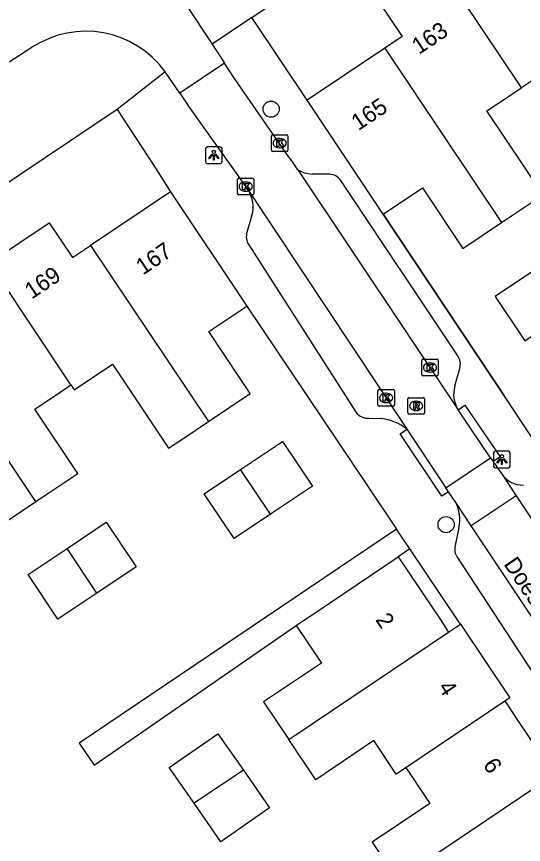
# Model space of a CAD drawing. Extents: x 158352 to 159489, y 383828 to 384597.
# Drawn here: x 158835 to 158865.6, y 384167.6 to 384217.6 of the extents above; entities that cross this region are included whole.
import ezdxf

# ---------------------------------------------------------------- set-up
doc = ezdxf.new("R2010")
doc.units = 0
for name, color, linetype in [('IMGEO_Boom', 7, 'Continuous'), ('IMGEO_Kolk', 7, 'Continuous'), ('IMGEO_Lichtpunt', 7, 'Continuous'), ('IMGEO_Muur', 7, 'Continuous'), ('IMGEO_Openbare_ruimte_label', 7, 'Continuous'), ('IMGEO_Pand', 7, 'Continuous'), ('IMGEO_Pand_nummerreeks', 7, 'Continuous'), ('IMGEO_Rijbaan_lokaal_open', 7, 'Continuous'), ('IMGEO_Rioolput', 7, 'Continuous'), ('IMGEO_Voetpad_open', 7, 'Continuous')]:
    doc.layers.add(name, color=color, linetype=linetype)

msp = doc.modelspace()

# ---------------------------------------------------------------- linework, layer by layer
at = {"layer": 'IMGEO_Boom'}
for centre in [(158850.367, 384212.043), (158860.955, 384186.927)]:
    msp.add_circle(centre, 0.489, dxfattribs=at)
at = {"layer": 'IMGEO_Kolk'}
for p, q in [((158850.381, 384209.562), (158850.381, 384210.414)), ((158850.456, 384210.488), (158851.308, 384210.488)), ((158850.869, 384210.268), (158850.894, 384210.268)), ((158851.382, 384210.414), (158851.382, 384209.562)), ((158850.892, 384209.708), (158850.867, 384209.708)), ((158851.308, 384209.488), (158850.456, 384209.488)), ((158848.323, 384206.935), (158848.323, 384207.787)), ((158848.398, 384207.861), (158849.25, 384207.861)), ((158848.811, 384207.641), (158848.836, 384207.641)), ((158849.324, 384207.787), (158849.324, 384206.935)), ((158848.834, 384207.081), (158848.809, 384207.081)), ((158849.25, 384206.861), (158848.398, 384206.861)), ((158859.482, 384195.998), (158859.482, 384196.85)), ((158859.557, 384196.924), (158860.409, 384196.924)), ((158859.97, 384196.704), (158859.995, 384196.704)), ((158860.483, 384196.85), (158860.483, 384195.998)), ((158859.993, 384196.144), (158859.968, 384196.144)), ((158860.409, 384195.924), (158859.557, 384195.924)), ((158856.899, 384195.086), (158857.751, 384195.086)), ((158856.824, 384194.16), (158856.824, 384195.012)), ((158857.312, 384194.866), (158857.337, 384194.866)), ((158857.825, 384195.012), (158857.825, 384194.16)), ((158857.751, 384194.086), (158856.899, 384194.086)), ((158857.335, 384194.306), (158857.31, 384194.306))]:
    msp.add_line(p, q, dxfattribs=at)
for points in [[(158850.381, 384209.562), (158850.381, 384210.414)], [(158850.456, 384210.488), (158851.308, 384210.488)], [(158850.702, 384210.188), (158850.825, 384210.188), (158850.825, 384210.037), (158850.955, 384210.188), (158851.119, 384210.188), (158850.973, 384210.037), (158851.126, 384209.788), (158850.974, 384209.788), (158850.889, 384209.952), (158850.825, 384209.885), (158850.825, 384209.788), (158850.702, 384209.788), (158850.702, 384210.188)], [(158851.382, 384210.414), (158851.382, 384209.562)], [(158851.308, 384209.488), (158850.456, 384209.488)], [(158848.323, 384206.935), (158848.323, 384207.787)], [(158848.398, 384207.861), (158849.25, 384207.861)], [(158849.324, 384207.787), (158849.324, 384206.935)], [(158848.644, 384207.561), (158848.767, 384207.561), (158848.767, 384207.41), (158848.897, 384207.561), (158849.061, 384207.561), (158848.915, 384207.41), (158849.068, 384207.161), (158848.916, 384207.161), (158848.831, 384207.325), (158848.767, 384207.258), (158848.767, 384207.161), (158848.644, 384207.161), (158848.644, 384207.561)], [(158849.25, 384206.861), (158848.398, 384206.861)], [(158859.482, 384195.998), (158859.482, 384196.85)], [(158859.557, 384196.924), (158860.409, 384196.924)], [(158859.803, 384196.624), (158859.926, 384196.624), (158859.926, 384196.473), (158860.056, 384196.624), (158860.22, 384196.624), (158860.074, 384196.473), (158860.227, 384196.224), (158860.075, 384196.224), (158859.99, 384196.388), (158859.926, 384196.321), (158859.926, 384196.224), (158859.803, 384196.224), (158859.803, 384196.624)], [(158860.483, 384196.85), (158860.483, 384195.998)], [(158860.409, 384195.924), (158859.557, 384195.924)], [(158856.899, 384195.086), (158857.751, 384195.086)], [(158856.824, 384194.16), (158856.824, 384195.012)], [(158857.145, 384194.786), (158857.268, 384194.786), (158857.268, 384194.635), (158857.398, 384194.786), (158857.562, 384194.786), (158857.416, 384194.635), (158857.569, 384194.386), (158857.417, 384194.386), (158857.332, 384194.55), (158857.268, 384194.483), (158857.268, 384194.386), (158857.145, 384194.386), (158857.145, 384194.786)], [(158857.825, 384195.012), (158857.825, 384194.16)], [(158857.751, 384194.086), (158856.899, 384194.086)]]:
    msp.add_lwpolyline(points, dxfattribs=at)
for centre, start, end in [((158850.458, 384210.412), 91.552, 178.448), ((158850.458, 384210.412), 91.552, 178.448), ((158851.306, 384210.412), 1.552, 88.448), ((158851.306, 384210.412), 1.552, 88.448), ((158850.458, 384209.564), 181.552, 268.448), ((158850.458, 384209.564), 181.552, 268.448), ((158851.306, 384209.564), 271.552, 358.448), ((158851.306, 384209.564), 271.552, 358.448), ((158848.4, 384207.785), 91.552, 178.448), ((158848.4, 384207.785), 91.552, 178.448), ((158849.248, 384207.785), 1.552, 88.448), ((158849.248, 384207.785), 1.552, 88.448), ((158848.4, 384206.937), 181.552, 268.448), ((158848.4, 384206.937), 181.552, 268.448), ((158849.248, 384206.937), 271.552, 358.448), ((158849.248, 384206.937), 271.552, 358.448), ((158859.559, 384196.848), 91.552, 178.448), ((158859.559, 384196.848), 91.552, 178.448), ((158860.407, 384196.848), 1.552, 88.448), ((158860.407, 384196.848), 1.552, 88.448), ((158859.559, 384196), 181.552, 268.448), ((158859.559, 384196), 181.552, 268.448), ((158860.407, 384196), 271.552, 358.448), ((158860.407, 384196), 271.552, 358.448), ((158856.901, 384195.01), 91.552, 178.448), ((158856.901, 384195.01), 91.552, 178.448), ((158857.749, 384195.01), 1.552, 88.448), ((158857.749, 384195.01), 1.552, 88.448), ((158856.901, 384194.162), 181.552, 268.448), ((158856.901, 384194.162), 181.552, 268.448), ((158857.749, 384194.162), 271.552, 358.448), ((158857.749, 384194.162), 271.552, 358.448)]:
    msp.add_arc(centre, 0.0765, start, end, dxfattribs=at)
for centre, major_axis, ratio, start_param, end_param in [((158850.868, 384209.988), (-0.387, 0.002), 0.722429, 4.712389, 7.853982), ((158850.893, 384209.988), (-0.39, 0.002), 0.717154, 1.570796, 4.712389), ((158848.81, 384207.361), (-0.387, 0.002), 0.722429, 4.712389, 7.853982), ((158848.835, 384207.361), (-0.39, 0.002), 0.717154, 1.570796, 4.712389), ((158859.969, 384196.424), (-0.387, 0.002), 0.722429, 4.712389, 7.853982), ((158859.994, 384196.424), (-0.39, 0.002), 0.717154, 1.570796, 4.712389), ((158857.311, 384194.586), (-0.387, 0.002), 0.722429, 4.712389, 7.853982), ((158857.336, 384194.586), (-0.39, 0.002), 0.717154, 1.570796, 4.712389)]:
    msp.add_ellipse(centre, major_axis=major_axis, ratio=ratio, start_param=start_param, end_param=end_param, dxfattribs=at)
at = {"layer": 'IMGEO_Lichtpunt'}
for p, q in [((158846.4, 384209.659), (158846.4, 384208.852)), ((158846.4, 384209.659), (158846.4, 384208.852)), ((158847.302, 384209.754), (158846.494, 384209.754)), ((158847.302, 384209.754), (158846.494, 384209.754)), ((158847.396, 384208.852), (158847.396, 384209.659)), ((158847.396, 384208.852), (158847.396, 384209.659)), ((158846.494, 384208.758), (158847.302, 384208.758)), ((158846.494, 384208.758), (158847.302, 384208.758)), ((158863.831, 384191.264), (158863.831, 384190.457)), ((158863.831, 384191.264), (158863.831, 384190.457)), ((158864.733, 384191.359), (158863.925, 384191.359)), ((158864.733, 384191.359), (158863.925, 384191.359)), ((158864.827, 384190.457), (158864.827, 384191.264)), ((158864.827, 384190.457), (158864.827, 384191.264)), ((158863.925, 384190.363), (158864.733, 384190.363)), ((158863.925, 384190.363), (158864.733, 384190.363))]:
    msp.add_line(p, q, dxfattribs=at)
for points in [[(158846.774, 384209.323), (158846.813, 384209.295), (158846.625, 384209.033), (158846.587, 384209.06), (158846.774, 384209.323)], [(158846.876, 384209.275), (158846.923, 384209.275), (158846.923, 384208.953), (158846.876, 384208.953), (158846.876, 384209.275)], [(158846.986, 384209.295), (158847.024, 384209.322), (158847.211, 384209.06), (158847.172, 384209.032), (158846.986, 384209.295)], [(158864.205, 384190.928), (158864.244, 384190.9), (158864.056, 384190.638), (158864.018, 384190.665), (158864.205, 384190.928)], [(158864.307, 384190.88), (158864.354, 384190.88), (158864.354, 384190.558), (158864.307, 384190.558), (158864.307, 384190.88)], [(158864.417, 384190.9), (158864.455, 384190.927), (158864.642, 384190.665), (158864.603, 384190.637), (158864.417, 384190.9)]]:
    msp.add_lwpolyline(points, dxfattribs=at)
for centre in [(158846.899, 384209.457), (158864.33, 384191.062)]:
    msp.add_circle(centre, 0.0994, dxfattribs=at)
for centre, start, end in [((158846.494, 384209.659), 90, 180), ((158846.494, 384209.659), 90, 180), ((158847.302, 384209.659), 0, 90), ((158847.302, 384209.659), 0, 90), ((158846.494, 384208.852), 180, 270), ((158846.494, 384208.852), 180, 270), ((158847.302, 384208.852), 270, 0), ((158847.302, 384208.852), 270, 360), ((158863.925, 384191.264), 90, 180), ((158863.925, 384191.264), 90, 180), ((158864.733, 384191.264), 0, 90), ((158864.733, 384191.264), 0, 90), ((158863.925, 384190.457), 180, 270), ((158863.925, 384190.457), 180, 270), ((158864.733, 384190.457), 270, 0), ((158864.733, 384190.457), 270, 360)]:
    msp.add_arc(centre, 0.0946, start, end, dxfattribs=at)
at = {"layer": 'IMGEO_Muur'}
for points in [[(158857.143, 384205.697), (158864.445, 384194.753)], [(158848.89, 384200.127), (158856.194, 384189.271)]]:
    msp.add_lwpolyline(points, dxfattribs=at)
at = {"layer": 'IMGEO_Pand'}
for points in [[(158860.858, 384220.299), (158860.447, 384220.913), (158856.885, 384218.53), (158858.292, 384216.428), (158857.246, 384215.728)], [(158865.517, 384213.338), (158865.421, 384213.482), (158860.858, 384220.299)], [(158857.246, 384215.728), (158852.538, 384212.577)], [(158857.246, 384215.728), (158864.304, 384205.184)], [(158870.027, 384211.237), (158869.947, 384211.183), (158867.58, 384214.719), (158865.517, 384213.338)], [(158864.304, 384205.184), (158866.129, 384206.406), (158866.824, 384206.871), (158863.43, 384211.941), (158865.517, 384213.338)], [(158857.143, 384205.697), (158852.538, 384212.577)], [(158857.143, 384205.697), (158859.52, 384207.288), (158861.974, 384203.624), (158864.304, 384205.184)], [(158844.268, 384207.036), (158839.443, 384203.809)], [(158844.268, 384207.036), (158848.89, 384200.127)], [(158833.777, 384202.052), (158833.309, 384202.752), (158836.934, 384205.178), (158838.343, 384203.073), (158839.443, 384203.809)], [(158839.443, 384203.809), (158846.568, 384193.158)], [(158866.251, 384202.276), (158863.921, 384200.716), (158865.718, 384198.032), (158868.047, 384199.592)], [(158838.25, 384195.367), (158838.209, 384195.428), (158833.777, 384202.052)], [(158846.568, 384193.158), (158849.108, 384194.859), (158846.605, 384198.598), (158848.89, 384200.127)], [(158836.124, 384188.317), (158835.871, 384188.696), (158829.052, 384198.891)], [(158838.25, 384195.367), (158838.444, 384195.077), (158840.76, 384196.626), (158844.159, 384191.546), (158844.954, 384192.078), (158846.568, 384193.158)], [(158836.124, 384188.317), (158838.661, 384190.014), (158836.059, 384193.902), (158837.602, 384194.934), (158838.101, 384195.267), (158838.25, 384195.367)], [(158848.514, 384190.249), (158851.055, 384191.95), (158852.863, 384189.249), (158850.321, 384187.548)], [(158828.991, 384188.758), (158831.225, 384190.253), (158833.634, 384186.651), (158836.124, 384188.317)], [(158850.321, 384187.548), (158848.127, 384186.079), (158846.319, 384188.78), (158848.514, 384190.249)], [(158850.321, 384187.548), (158848.514, 384190.249)], [(158838.017, 384185.488), (158840.39, 384187.076), (158842.198, 384184.375), (158839.824, 384182.786)], [(158839.824, 384182.786), (158837.462, 384181.205), (158835.654, 384183.906), (158838.017, 384185.488)], [(158839.824, 384182.786), (158838.017, 384185.488)], [(158851.882, 384180.832), (158853.899, 384182.187), (158858.049, 384184.975)], [(158858.049, 384184.975), (158860.667, 384181.079), (158861.009, 384180.57), (158861.106, 384180.426)], [(158851.882, 384180.832), (158853.411, 384178.559), (158849.91, 384176.206), (158851.438, 384173.932)], [(158861.106, 384180.426), (158861.821, 384180.907)], [(158861.821, 384180.907), (158864.81, 384176.459), (158864.513, 384176.259)], [(158851.438, 384173.932), (158851.682, 384174.096), (158861.106, 384180.426)], [(158864.513, 384176.259), (158858.517, 384172.232)], [(158864.513, 384176.259), (158864.588, 384176.147), (158865.246, 384175.168), (158867.501, 384171.811)], [(158845.706, 384170.082), (158844.204, 384172.235), (158847.151, 384174.283), (158848.685, 384172.083)], [(158858.517, 384172.232), (158857.94, 384171.845), (158856.581, 384173.868), (158853.067, 384171.507), (158851.438, 384173.932)], [(158848.685, 384172.083), (158845.706, 384170.082)], [(158848.685, 384172.083), (158850.275, 384169.804), (158847.328, 384167.756), (158845.706, 384170.082)], [(158858.517, 384172.232), (158858.716, 384171.937), (158858.956, 384171.581), (158859.97, 384170.072), (158856.487, 384167.731), (158858.024, 384165.444)], [(158858.024, 384165.444), (158858.355, 384165.667), (158867.501, 384171.811)]]:
    msp.add_lwpolyline(points, dxfattribs=at)
at = {"layer": 'IMGEO_Rijbaan_lokaal_open'}
for points in [[(158845.198, 384218.378), (158846.791, 384215.962)], [(158835.895, 384215.779), (158834.508, 384214.879)], [(158846.791, 384215.962), (158847.546, 384214.816)], [(158847.546, 384214.816), (158844.837, 384213.001)], [(158851.983, 384208.383), (158851.589, 384208.974), (158851.354, 384209.268), (158848.141, 384213.898), (158847.546, 384214.816)], [(158844.837, 384213.001), (158843.962, 384214.297)], [(158844.837, 384213.001), (158845.444, 384212.097), (158848.992, 384207.115)], [(158851.983, 384208.383), (158861.676, 384193.862)], [(158848.992, 384207.115), (158858.439, 384192.912), (158858.586, 384192.689)], [(158863.65, 384190.966), (158861.676, 384193.862)], [(158858.586, 384192.689), (158860.943, 384189.158)], [(158860.943, 384189.158), (158863.65, 384190.966)], [(158863.65, 384190.966), (158863.807, 384190.736)], [(158863.807, 384190.736), (158864.301, 384190.011)], [(158864.301, 384190.011), (158865.197, 384188.669)], [(158861.106, 384188.914), (158860.943, 384189.158)], [(158861.542, 384188.261), (158861.106, 384188.914)], [(158865.197, 384188.669), (158862.48, 384186.854)], [(158865.197, 384188.669), (158879, 384168.028)], [(158862.48, 384186.854), (158861.542, 384188.261)], [(158876.351, 384166.052), (158876.113, 384166.409), (158862.48, 384186.854)]]:
    msp.add_lwpolyline(points, dxfattribs=at)
msp.add_arc((158839.152, 384210.813), 5.939, 35.921, 123.2594, dxfattribs=at)
at = {"layer": 'IMGEO_Rioolput'}
for p, q in [((158858.72, 384194.6), (158859.572, 384194.6)), ((158858.645, 384193.674), (158858.645, 384194.526)), ((158859.133, 384194.38), (158859.158, 384194.38)), ((158859.646, 384194.526), (158859.646, 384193.674)), ((158859.572, 384193.6), (158858.72, 384193.6)), ((158859.156, 384193.82), (158859.131, 384193.82))]:
    msp.add_line(p, q, dxfattribs=at)
for points in [[(158858.72, 384194.6), (158859.572, 384194.6)], [(158858.645, 384193.674), (158858.645, 384194.526)], [(158859.234, 384194.298), (158858.982, 384194.3), (158858.982, 384193.9)], [(158859.16, 384194.219), (158859.106, 384194.219), (158859.106, 384194.138)], [(158859.106, 384194.138), (158859.158, 384194.138)], [(158859.646, 384194.526), (158859.646, 384193.674)], [(158859.572, 384193.6), (158858.72, 384193.6)], [(158858.982, 384193.9), (158859.106, 384193.9), (158859.106, 384194.062), (158859.117, 384194.062)], [(158859.164, 384194.033), (158859.235, 384193.9), (158859.375, 384193.9), (158859.31, 384194.026)]]:
    msp.add_lwpolyline(points, dxfattribs=at)
for centre, radius, start, end in [((158858.722, 384194.524), 0.0765, 91.552, 178.448), ((158858.722, 384194.524), 0.0765, 91.552, 178.448), ((158859.57, 384194.524), 0.0765, 1.552, 88.448), ((158859.57, 384194.524), 0.0765, 1.552, 88.448), ((158859.142, 384194.327), 0.19, 274.7715, 282.9687), ((158859.166, 384194.123), 0.0964, 77.0061, 93.1865), ((158859.18, 384194.18), 0.0378, 276.6634, 79.6772), ((158859.233, 384194.188), 0.109, 350.3612, 89.416), ((158859.231, 384194.188), 0.112, 277.5842, 350.9817), ((158859.215, 384193.973), 0.108, 29.5134, 73.7905), ((158858.722, 384193.676), 0.0765, 181.552, 268.448), ((158858.722, 384193.676), 0.0765, 181.552, 268.448), ((158859.116, 384194.009), 0.0533, 26.0293, 88.6989), ((158859.57, 384193.676), 0.0765, 271.552, 358.448), ((158859.57, 384193.676), 0.0765, 271.552, 358.448)]:
    msp.add_arc(centre, radius, start, end, dxfattribs=at)
for centre, major_axis, ratio, start_param, end_param in [((158859.132, 384194.1), (-0.387, 0.002), 0.722429, 4.712389, 7.853982), ((158859.157, 384194.1), (-0.39, 0.002), 0.717154, 1.570796, 4.712389)]:
    msp.add_ellipse(centre, major_axis=major_axis, ratio=ratio, start_param=start_param, end_param=end_param, dxfattribs=at)
at = {"layer": 'IMGEO_Voetpad_open'}
for points in [[(158849.203, 384217.574), (158932.003, 384272.919)], [(158849.203, 384217.574), (158846.791, 384215.962)], [(158852.538, 384212.577), (158849.203, 384217.574)], [(158843.962, 384214.297), (158841.042, 384212.024)], [(158841.042, 384212.024), (158794.638, 384180.916), (158793.73, 384180.171)], [(158841.042, 384212.024), (158843.27, 384208.645), (158844.268, 384207.036)], [(158853.902, 384208.104), (158852.841, 384208.113)], [(158861.661, 384197.139), (158854.581, 384207.733)], [(158849.208, 384205.629), (158848.901, 384204.594)], [(158866.244, 384192.057), (158864.445, 384194.753), (158857.143, 384205.697)], [(158849.015, 384203.839), (158855.509, 384193.706)], [(158848.89, 384200.127), (158856.194, 384189.271), (158857.959, 384186.647)], [(158861.481, 384195.306), (158861.783, 384196.363)], [(158861.676, 384193.862), (158862.088, 384194.142), (158864.22, 384191.017), (158863.807, 384190.736)], [(158856.28, 384193.351), (158857.03, 384193.335)], [(158861.106, 384188.914), (158860.691, 384188.637), (158858.172, 384192.413), (158858.586, 384192.689)], [(158857.959, 384186.647), (158838.748, 384173.722), (158839.665, 384172.375), (158851.882, 384180.832)], [(158858.762, 384185.454), (158857.959, 384186.647)], [(158861.727, 384186.75), (158861.495, 384185.664)], [(158858.762, 384185.454), (158858.049, 384184.975)], [(158861.821, 384180.907), (158861.724, 384181.051), (158858.762, 384185.454)], [(158861.63, 384184.958), (158873.249, 384167.231)]]:
    msp.add_lwpolyline(points, dxfattribs=at)
for centre, radius, start, end in [((158852.994, 384210.099), 1.992, 239.4806, 265.5833), ((158853.892, 384207.279), 0.825, 33.3785, 89.3178), ((158847.489, 384206.138), 1.793, 343.5168, 33.024), ((158849.765, 384204.338), 0.901, 163.5045, 213.6683), ((158860.878, 384196.618), 0.94, 344.237, 33.6324), ((158863.247, 384194.809), 1.835, 164.2975, 211.0841), ((158856.234, 384194.267), 0.917, 217.7032, 272.8502), ((158856.693, 384190.326), 3.028, 51.299, 83.6077), ((158865.624, 384190.915), 1.602, 214.359, 270.4709), ((158859.547, 384187.25), 2.236, 347.0806, 26.88), ((158862.397, 384185.471), 0.923, 167.9058, 213.7448)]:
    msp.add_arc(centre, radius, start, end, dxfattribs=at)

# ---------------------------------------------------------------- texts
at = {"layer": 'IMGEO_Openbare_ruimte_label'}
msp.add_text('Doesburgstraat', height=1, rotation=303.992, dxfattribs=at).set_placement((158864.405, 384184.54))
at = {"layer": 'IMGEO_Pand_nummerreeks'}
for s, rotation, p in [('163', 33.7988, (158859.31, 384215.315)), ('165', 33.7933, (158855.646, 384210.711)), ('167', 33.7796, (158842.609, 384201.98)), ('169', 33.8102, (158835.878, 384200.523)), ('2', 303.9017, (158856.652, 384181.173)), ('4', 303.9017, (158860.439, 384177.083)), ('6', 303.896, (158863.155, 384172.399))]:
    msp.add_text(s, height=1, rotation=rotation, dxfattribs=at).set_placement(p)

doc.saveas('drawing.dxf')
